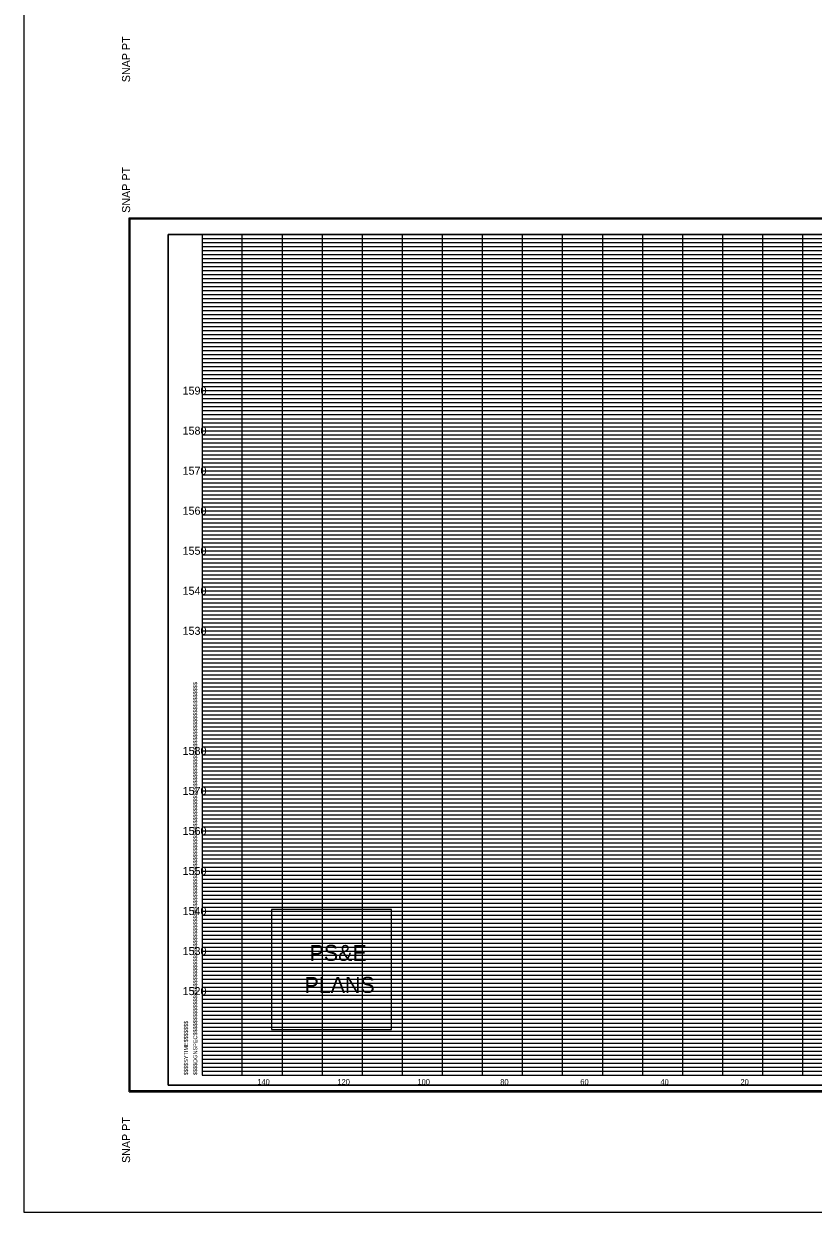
# Model space of a CAD drawing. Extents: x 955 to 1375, y 1248 to 3657.
# Drawn here: x 955.4 to 1152.6, y 1505.8 to 1802.7 of the extents above; entities that cross this region are included whole.
import ezdxf

# ---------------------------------------------------------------- set-up
doc = ezdxf.new("R2010")
doc.units = 0
for name, color, linetype in [('DESIGN - SHEET - Corner Text', 7, 'Continuous'), ('DESIGN - SHEET - Light Grid', 7, 'Continuous'), ('DESIGN - SHEET - Linework', 7, 'Continuous'), ('DESIGN - SHEET - Plot Shape', 7, 'Continuous'), ('DESIGN - TYPICAL - Text', 7, 'Continuous'), ('DESIGN - UTILITIES - Cable (Overhead) with Text', 7, 'Continuous'), ('SURVEY - NON-TRANSPORTATION - Features Text', 7, 'Continuous')]:
    doc.layers.add(name, color=color, linetype=linetype)

# ---------------------------------------------------------------- blocks, each defined once
blk = doc.blocks.new('XSTSHT')
at = {"layer": 'DESIGN - SHEET - Light Grid'}
for p, q in [((0, 20.9), (8, 20.9)), ((0, 20.8), (8, 20.8)), ((8, 20.9), (16, 20.9)), ((8, 20.8), (16, 20.8)), ((0, 20.7), (8, 20.7)), ((0, 20.6), (8, 20.6)), ((0, 20.5), (8, 20.5)), ((8, 20.7), (16, 20.7)), ((8, 20.6), (16, 20.6)), ((8, 20.5), (16, 20.5)), ((0, 20.4), (8, 20.4)), ((0, 20.3), (8, 20.3)), ((0, 20.2), (8, 20.2)), ((8, 20.4), (16, 20.4)), ((8, 20.3), (16, 20.3)), ((8, 20.2), (16, 20.2)), ((0, 20.1), (8, 20.1)), ((0, 19.9), (8, 19.9)), ((8, 20.1), (16, 20.1)), ((8, 19.9), (16, 19.9)), ((0, 19.8), (8, 19.8)), ((0, 19.7), (8, 19.7)), ((0, 19.6), (8, 19.6)), ((8, 19.8), (16, 19.8)), ((8, 19.7), (16, 19.7)), ((8, 19.6), (16, 19.6)), ((0, 19.5), (8, 19.5)), ((0, 19.4), (8, 19.4)), ((0, 19.3), (8, 19.3)), ((8, 19.5), (16, 19.5)), ((8, 19.4), (16, 19.4)), ((8, 19.3), (16, 19.3)), ((0, 19.2), (8, 19.2)), ((0, 19.1), (8, 19.1)), ((8, 19.2), (16, 19.2)), ((8, 19.1), (16, 19.1)), ((0, 18.9), (8, 18.9)), ((0, 18.8), (8, 18.8)), ((8, 18.9), (16, 18.9)), ((8, 18.8), (16, 18.8)), ((0, 18.7), (8, 18.7)), ((0, 18.6), (8, 18.6)), ((0, 18.5), (8, 18.5)), ((8, 18.7), (16, 18.7)), ((8, 18.6), (16, 18.6)), ((8, 18.5), (16, 18.5)), ((0, 18.4), (8, 18.4)), ((0, 18.3), (8, 18.3)), ((0, 18.2), (8, 18.2)), ((8, 18.4), (16, 18.4)), ((8, 18.3), (16, 18.3)), ((8, 18.2), (16, 18.2)), ((0, 18.1), (8, 18.1)), ((0, 17.9), (8, 17.9)), ((8, 18.1), (16, 18.1)), ((8, 17.9), (16, 17.9)), ((0, 17.8), (8, 17.8)), ((0, 17.7), (8, 17.7)), ((0, 17.6), (8, 17.6)), ((8, 17.8), (16, 17.8)), ((8, 17.7), (16, 17.7)), ((8, 17.6), (16, 17.6)), ((0, 17.5), (8, 17.5)), ((0, 17.4), (8, 17.4)), ((0, 17.3), (8, 17.3)), ((8, 17.5), (16, 17.5)), ((8, 17.4), (16, 17.4)), ((8, 17.3), (16, 17.3)), ((0, 17.2), (8, 17.2)), ((0, 17.1), (8, 17.1)), ((8, 17.2), (16, 17.2)), ((8, 17.1), (16, 17.1)), ((0, 16.9), (8, 16.9)), ((0, 16.8), (8, 16.8)), ((0, 16.7), (8, 16.7)), ((8, 16.9), (16, 16.9)), ((8, 16.8), (16, 16.8)), ((8, 16.7), (16, 16.7)), ((0, 16.6), (8, 16.6)), ((0, 16.5), (8, 16.5)), ((0, 16.4), (8, 16.4)), ((8, 16.6), (16, 16.6)), ((8, 16.5), (16, 16.5)), ((8, 16.4), (16, 16.4)), ((0, 16.3), (8, 16.3)), ((0, 16.2), (8, 16.2)), ((0, 16.1), (8, 16.1)), ((8, 16.3), (16, 16.3)), ((8, 16.2), (16, 16.2)), ((8, 16.1), (16, 16.1)), ((0, 15.9), (8, 15.9)), ((0, 15.8), (8, 15.8)), ((8, 15.9), (16, 15.9)), ((8, 15.8), (16, 15.8)), ((0, 15.7), (8, 15.7)), ((0, 15.6), (8, 15.6)), ((0, 15.5), (8, 15.5)), ((8, 15.7), (16, 15.7)), ((8, 15.6), (16, 15.6)), ((8, 15.5), (16, 15.5)), ((0, 15.4), (8, 15.4)), ((0, 15.3), (8, 15.3)), ((0, 15.2), (8, 15.2)), ((8, 15.4), (16, 15.4)), ((8, 15.3), (16, 15.3)), ((8, 15.2), (16, 15.2)), ((0, 15.1), (8, 15.1)), ((0, 14.9), (8, 14.9)), ((8, 15.1), (16, 15.1)), ((8, 14.9), (16, 14.9)), ((0, 14.8), (8, 14.8)), ((0, 14.7), (8, 14.7)), ((0, 14.6), (8, 14.6)), ((8, 14.8), (16, 14.8)), ((8, 14.7), (16, 14.7)), ((8, 14.6), (16, 14.6)), ((0, 14.5), (8, 14.5)), ((0, 14.4), (8, 14.4)), ((0, 14.3), (8, 14.3)), ((8, 14.5), (16, 14.5)), ((8, 14.4), (16, 14.4)), ((8, 14.3), (16, 14.3)), ((0, 14.2), (8, 14.2)), ((0, 14.1), (8, 14.1)), ((8, 14.2), (16, 14.2)), ((8, 14.1), (16, 14.1)), ((0, 13.9), (8, 13.9)), ((0, 13.8), (8, 13.8)), ((0, 13.7), (8, 13.7)), ((8, 13.9), (16, 13.9)), ((8, 13.8), (16, 13.8)), ((8, 13.7), (16, 13.7)), ((0, 13.6), (8, 13.6)), ((0, 13.5), (8, 13.5)), ((0, 13.4), (8, 13.4)), ((8, 13.6), (16, 13.6)), ((8, 13.5), (16, 13.5)), ((8, 13.4), (16, 13.4)), ((0, 13.3), (8, 13.3)), ((0, 13.2), (8, 13.2)), ((0, 13.1), (8, 13.1)), ((8, 13.3), (16, 13.3)), ((8, 13.2), (16, 13.2)), ((8, 13.1), (16, 13.1)), ((0, 12.9), (8, 12.9)), ((0, 12.8), (8, 12.8)), ((8, 12.9), (16, 12.9)), ((8, 12.8), (16, 12.8)), ((0, 12.7), (8, 12.7)), ((0, 12.6), (8, 12.6)), ((0, 12.5), (8, 12.5)), ((8, 12.7), (16, 12.7)), ((8, 12.6), (16, 12.6)), ((8, 12.5), (16, 12.5)), ((0, 12.4), (8, 12.4)), ((0, 12.3), (8, 12.3)), ((0, 12.2), (8, 12.2)), ((8, 12.4), (16, 12.4)), ((8, 12.3), (16, 12.3)), ((8, 12.2), (16, 12.2)), ((0, 12.1), (8, 12.1)), ((0, 11.9), (8, 11.9)), ((8, 12.1), (16, 12.1)), ((8, 11.9), (16, 11.9)), ((0, 11.8), (8, 11.8)), ((0, 11.7), (8, 11.7)), ((0, 11.6), (8, 11.6)), ((8, 11.8), (16, 11.8)), ((8, 11.7), (16, 11.7)), ((8, 11.6), (16, 11.6)), ((0, 11.5), (8, 11.5)), ((0, 11.4), (8, 11.4)), ((0, 11.3), (8, 11.3)), ((8, 11.5), (16, 11.5)), ((8, 11.4), (16, 11.4)), ((8, 11.3), (16, 11.3)), ((0, 11.2), (8, 11.2)), ((0, 11.1), (8, 11.1)), ((8, 11.2), (16, 11.2)), ((8, 11.1), (16, 11.1)), ((0, 10.9), (8, 10.9)), ((0, 10.8), (8, 10.8)), ((0, 10.7), (8, 10.7)), ((8, 10.9), (16, 10.9)), ((8, 10.8), (16, 10.8)), ((8, 10.7), (16, 10.7)), ((0, 10.6), (8, 10.6)), ((0, 10.5), (8, 10.5)), ((0, 10.4), (8, 10.4)), ((8, 10.6), (16, 10.6)), ((8, 10.5), (16, 10.5)), ((8, 10.4), (16, 10.4)), ((0, 10.3), (8, 10.3)), ((0, 10.2), (8, 10.2)), ((0, 10.1), (8, 10.1)), ((8, 10.3), (16, 10.3)), ((8, 10.2), (16, 10.2)), ((8, 10.1), (16, 10.1)), ((0, 9.9), (8, 9.9)), ((0, 9.8), (8, 9.8)), ((8, 9.9), (16, 9.9)), ((8, 9.8), (16, 9.8)), ((0, 9.7), (8, 9.7)), ((0, 9.6), (8, 9.6)), ((8, 9.7), (16, 9.7)), ((8, 9.6), (16, 9.6)), ((0, 9.5), (8, 9.5)), ((0, 9.4), (8, 9.4)), ((0, 9.3), (8, 9.3)), ((8, 9.5), (16, 9.5)), ((8, 9.4), (16, 9.4)), ((8, 9.3), (16, 9.3)), ((0, 9.2), (8, 9.2)), ((0, 9.1), (8, 9.1)), ((8, 9.2), (16, 9.2)), ((8, 9.1), (16, 9.1)), ((0, 8.9), (8, 8.9)), ((0, 8.8), (8, 8.8)), ((0, 8.7), (8, 8.7)), ((8, 8.9), (16, 8.9)), ((8, 8.8), (16, 8.8)), ((8, 8.7), (16, 8.7)), ((0, 8.6), (8, 8.6)), ((0, 8.5), (8, 8.5)), ((0, 8.4), (8, 8.4)), ((8, 8.6), (16, 8.6)), ((8, 8.5), (16, 8.5)), ((8, 8.4), (16, 8.4)), ((0, 8.3), (8, 8.3)), ((0, 8.2), (8, 8.2)), ((0, 8.1), (8, 8.1)), ((8, 8.3), (16, 8.3)), ((8, 8.2), (16, 8.2)), ((8, 8.1), (16, 8.1)), ((0, 7.9), (8, 7.9)), ((0, 7.8), (8, 7.8)), ((8, 7.9), (16, 7.9)), ((8, 7.8), (16, 7.8)), ((0, 7.7), (8, 7.7)), ((0, 7.6), (8, 7.6)), ((0, 7.5), (8, 7.5)), ((8, 7.7), (16, 7.7)), ((8, 7.6), (16, 7.6)), ((8, 7.5), (16, 7.5)), ((0, 7.4), (8, 7.4)), ((0, 7.3), (8, 7.3)), ((0, 7.2), (8, 7.2)), ((8, 7.4), (16, 7.4)), ((8, 7.3), (16, 7.3)), ((8, 7.2), (16, 7.2)), ((0, 7.1), (8, 7.1)), ((0, 6.9), (8, 6.9)), ((8, 7.1), (16, 7.1)), ((8, 6.9), (16, 6.9)), ((0, 6.8), (8, 6.8)), ((0, 6.7), (8, 6.7)), ((0, 6.6), (8, 6.6)), ((8, 6.8), (16, 6.8)), ((8, 6.7), (16, 6.7)), ((8, 6.6), (16, 6.6)), ((0, 6.5), (8, 6.5)), ((0, 6.4), (8, 6.4)), ((0, 6.3), (8, 6.3)), ((8, 6.5), (16, 6.5)), ((8, 6.4), (16, 6.4)), ((8, 6.3), (16, 6.3)), ((0, 6.2), (8, 6.2)), ((0, 6.1), (8, 6.1)), ((8, 6.2), (16, 6.2)), ((8, 6.1), (16, 6.1)), ((0, 5.9), (8, 5.9)), ((0, 5.8), (8, 5.8)), ((0, 5.7), (8, 5.7)), ((8, 5.9), (16, 5.9)), ((8, 5.8), (16, 5.8)), ((8, 5.7), (16, 5.7)), ((0, 5.6), (8, 5.6)), ((0, 5.5), (8, 5.5)), ((0, 5.4), (8, 5.4)), ((8, 5.6), (16, 5.6)), ((8, 5.5), (16, 5.5)), ((8, 5.4), (16, 5.4)), ((0, 5.3), (8, 5.3)), ((0, 5.2), (8, 5.2)), ((0, 5.1), (8, 5.1)), ((8, 5.3), (16, 5.3)), ((8, 5.2), (16, 5.2)), ((8, 5.1), (16, 5.1)), ((0, 4.9), (8, 4.9)), ((0, 4.8), (8, 4.8)), ((8, 4.9), (16, 4.9)), ((8, 4.8), (16, 4.8)), ((0, 4.7), (8, 4.7)), ((0, 4.6), (8, 4.6)), ((0, 4.5), (8, 4.5)), ((8, 4.7), (16, 4.7)), ((8, 4.6), (16, 4.6)), ((8, 4.5), (16, 4.5)), ((0, 4.4), (8, 4.4)), ((0, 4.3), (8, 4.3)), ((0, 4.2), (8, 4.2)), ((8, 4.4), (16, 4.4)), ((8, 4.3), (16, 4.3)), ((8, 4.2), (16, 4.2)), ((0, 4.1), (8, 4.1)), ((0, 3.9), (8, 3.9)), ((8, 4.1), (16, 4.1)), ((8, 3.9), (16, 3.9)), ((0, 3.8), (8, 3.8)), ((0, 3.7), (8, 3.7)), ((0, 3.6), (8, 3.6)), ((8, 3.8), (16, 3.8)), ((8, 3.7), (16, 3.7)), ((8, 3.6), (16, 3.6)), ((0, 3.5), (8, 3.5)), ((0, 3.4), (8, 3.4)), ((0, 3.3), (8, 3.3)), ((8, 3.5), (16, 3.5)), ((8, 3.4), (16, 3.4)), ((8, 3.3), (16, 3.3)), ((0, 3.2), (8, 3.2)), ((0, 3.1), (8, 3.1)), ((8, 3.2), (16, 3.2)), ((8, 3.1), (16, 3.1)), ((0, 2.9), (8, 2.9)), ((0, 2.8), (8, 2.8)), ((0, 2.7), (8, 2.7)), ((8, 2.9), (16, 2.9)), ((8, 2.8), (16, 2.8)), ((8, 2.7), (16, 2.7)), ((0, 2.6), (8, 2.6)), ((0, 2.5), (8, 2.5)), ((0, 2.4), (8, 2.4)), ((8, 2.6), (16, 2.6)), ((8, 2.5), (16, 2.5)), ((8, 2.4), (16, 2.4)), ((0, 2.3), (8, 2.3)), ((0, 2.2), (8, 2.2)), ((0, 2.1), (8, 2.1)), ((8, 2.3), (16, 2.3)), ((8, 2.2), (16, 2.2)), ((8, 2.1), (16, 2.1)), ((0, 1.9), (8, 1.9)), ((0, 1.8), (8, 1.8)), ((8, 1.9), (16, 1.9)), ((8, 1.8), (16, 1.8)), ((0, 1.7), (8, 1.7)), ((0, 1.6), (8, 1.6)), ((0, 1.5), (8, 1.5)), ((8, 1.7), (16, 1.7)), ((8, 1.6), (16, 1.6)), ((8, 1.5), (16, 1.5)), ((0, 1.4), (8, 1.4)), ((0, 1.3), (8, 1.3)), ((0, 1.2), (8, 1.2)), ((8, 1.4), (16, 1.4)), ((8, 1.3), (16, 1.3)), ((8, 1.2), (16, 1.2)), ((0, 1.1), (8, 1.1)), ((0, 0.9), (8, 0.9)), ((8, 1.1), (16, 1.1)), ((8, 0.9), (16, 0.9)), ((0, 0.8), (8, 0.8)), ((0, 0.7), (8, 0.7)), ((0, 0.6), (8, 0.6)), ((8, 0.8), (16, 0.8)), ((8, 0.7), (16, 0.7)), ((8, 0.6), (16, 0.6)), ((0, 0.5), (8, 0.5)), ((0, 0.4), (8, 0.4)), ((0, 0.3), (8, 0.3)), ((8, 0.5), (16, 0.5)), ((8, 0.4), (16, 0.4)), ((8, 0.3), (16, 0.3)), ((0, 0.2), (8, 0.2)), ((0, 0.1), (8, 0.1)), ((8, 0.2), (16, 0.2)), ((8, 0.1), (16, 0.1))]:
    blk.add_line(p, q, dxfattribs=at)
at = {"layer": 'DESIGN - SHEET - Linework'}
for p, q in [((-1.823, -0.414), (-1.823, 21.414)), ((-1.823, 21.414), (32.217, 21.414)), ((1, 0), (1, 21)), ((2, 0), (2, 21)), ((3, 0), (3, 21)), ((4, 0), (4, 21)), ((5, 0), (5, 21)), ((6, 0), (6, 21)), ((7, 0), (7, 21)), ((8, 0), (8, 21)), ((9, 0), (9, 21)), ((10, 0), (10, 21)), ((11, 0), (11, 21)), ((12, 0), (12, 21)), ((13, 0), (13, 21)), ((14, 0), (14, 21)), ((15, 0), (15, 21)), ((0, 20), (28, 20)), ((0, 19), (32, 19)), ((0, 18), (32, 18)), ((0, 17), (32, 17)), ((0, 16), (32, 16)), ((0, 15), (32, 15)), ((0, 14), (32, 14)), ((0, 13), (32, 13)), ((0, 12), (32, 12)), ((0, 11), (32, 11)), ((0, 10), (32, 10)), ((0, 9), (32, 9)), ((0, 8), (32, 8)), ((0, 7), (32, 7)), ((0, 6), (32, 6)), ((0, 5), (32, 5)), ((0, 4), (32, 4)), ((0, 3), (32, 3)), ((0, 2), (32, 2)), ((0, 1), (32, 1)), ((-1.823, -0.414), (32.217, -0.414))]:
    blk.add_line(p, q, dxfattribs=at)
blk.add_lwpolyline([(0, 21), (0, 0), (32, 0), (32, 21), (0, 21)], dxfattribs=at)
at = {"layer": 'DESIGN - SHEET - Plot Shape'}
for points in [[(-1.803, 21.394), (32.197, 21.394), (32.197, -0.394), (-1.803, -0.394)], [(-0.85, 21), (32, 21), (32, -0.25), (-0.85, -0.25)]]:
    blk.add_lwpolyline(points, close=True, dxfattribs=at)
at = {"layer": 'DESIGN - SHEET - Corner Text'}
for s, height, p in [('  SNAP PT', 0.2, (-1.803, 21.394)), ('$$$$DGNSPEC$$$$$$$$$$$$$$$$$$$$$$$$$$$$$$$$$$$$$$$$$$$$$$$$$$$$$$$$$$$$$$$$$$$$$$$$$$$$$$$$$$$$$$$$$$$$$$$$$$$$$$$$$$$$$$$$$$$', 0.100002, (-0.126, 0)), ('$$$$SYTIME$$$$$$$', 0.1, (-0.358, 0)), ('SNAP PT  ', 0.2, (-1.803, -2.194))]:
    blk.add_text(s, height=height, rotation=90, dxfattribs=at).set_placement(p)

msp = doc.modelspace()

# ---------------------------------------------------------------- linework, layer by layer
at = {"layer": 'DESIGN - SHEET - Corner Text'}
msp.add_lwpolyline([(1017.29, 1581.38), (1017.29, 1551.38), (1047.29, 1551.38), (1047.29, 1581.38)], close=True, dxfattribs=at)
at = {"layer": 'DESIGN - SHEET - Plot Shape'}
msp.add_lwpolyline([(991.5, 1537.5), (1320, 1537.5), (1320, 1750), (991.5, 1750)], close=True, dxfattribs=at)
at = {"layer": 'SURVEY - NON-TRANSPORTATION - Features Text'}
msp.add_lwpolyline([(955.41, 1505.76), (1344.98, 1505.76), (1344.98, 3398.01), (955.41, 3398.01)], close=True, dxfattribs=at)

# ---------------------------------------------------------------- block references
at = {"layer": 'DESIGN - UTILITIES - Cable (Overhead) with Text', "xscale": 10, "yscale": 10}
for p in [(1000, 1810), (1000, 1540)]:
    msp.add_blockref('XSTSHT', p, dxfattribs=at)

# ---------------------------------------------------------------- texts
at = {"layer": 'DESIGN - SHEET - Corner Text'}
for s, p in [('PS&E', (1026.8, 1568.55)), ('PLANS', (1025.52, 1560.55))]:
    msp.add_text(s, height=4, dxfattribs=at).set_placement(p)
at = {"layer": 'DESIGN - TYPICAL - Text'}
for s, height, p in [('     1590     ', 2, (991.37, 1710)), ('     1580     ', 2, (991.37, 1700)), ('     1570     ', 2, (991.37, 1690)), ('     1560     ', 2, (991.37, 1680)), ('     1550     ', 2, (991.37, 1670)), ('     1540     ', 2, (991.37, 1660)), ('     1530     ', 2, (991.37, 1650)), ('     1580     ', 2, (991.37, 1620)), ('     1570     ', 2, (991.37, 1610)), ('     1560     ', 2, (991.37, 1600)), ('     1550     ', 2, (991.37, 1590)), ('     1540     ', 2, (991.37, 1580)), ('     1530     ', 2, (991.37, 1570)), ('     1520     ', 2, (991.37, 1560)), ('     140     ', 1.4, (1011.14, 1537.6)), ('     120     ', 1.4, (1031.14, 1537.6)), ('     100     ', 1.4, (1051.14, 1537.6)), ('     80     ', 1.4, (1071.82, 1537.6)), ('     60     ', 1.4, (1091.82, 1537.6)), ('     40     ', 1.4, (1111.82, 1537.6)), ('     20     ', 1.4, (1131.82, 1537.6))]:
    msp.add_text(s, height=height, dxfattribs=at).set_placement(p)

doc.saveas('drawing.dxf')
